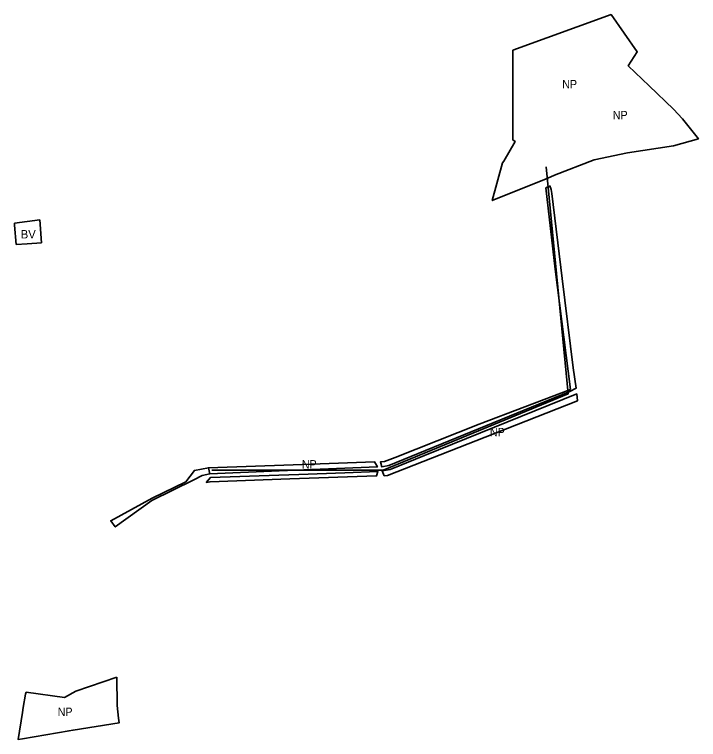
# Model space of a CAD drawing. Extents: x -650276 to -642489, y -1074311 to -1066658.
# Drawn here: x -643464 to -642489, y -1070593 to -1069560 of the extents above; entities that cross this region are included whole.
import ezdxf

# ---------------------------------------------------------------- set-up
doc = ezdxf.new("R2010")
doc.units = 0
doc.header["$LTSCALE"] = 4.8
for name, color, linetype, lineweight in [('15', 7, 'Continuous', 35), ('3', 7, 'Continuous', 35), ('48', 7, 'Continuous', 35), ('54', 7, 'Continuous', 35)]:
    doc.layers.add(name, color=color, linetype=linetype, lineweight=lineweight)
doc.layers.add('62', color=7, linetype='Continuous')

msp = doc.modelspace()

# ---------------------------------------------------------------- linework, layer by layer
at = {"layer": '15', "lineweight": 13}
for points in [[(-643461.327, -1069887.84), (-643445.37, -1069886.7), (-643425.253, -1069885.25), (-643427.6, -1069852.59), (-643463.51, -1069857.44)], [(-643463.51, -1069857.44), (-643463.31, -1069860.18), (-643461.327, -1069887.84)]]:
    msp.add_lwpolyline(points, dxfattribs=at)
at = {"layer": '3'}
msp.add_lwpolyline([(-643461.327, -1069887.84), (-643445.37, -1069886.7), (-643425.253, -1069885.25), (-643427.6, -1069852.59), (-643463.51, -1069857.44), (-643463.31, -1069860.18)], close=True, dxfattribs=at)
at = {"layer": '48'}
for points in [[(-642589.86, -1069757.1), (-642524.14, -1069746.8), (-642488.71, -1069736.85), (-642511.74, -1069708.63), (-642524.24, -1069694.66), (-642559.13, -1069661.18), (-642588.93, -1069632.86), (-642576, -1069613), (-642613.34, -1069559.68), (-642753.18, -1069610.65), (-642753.25, -1069738.59), (-642750.08, -1069740.57), (-642766.27, -1069769), (-642767.89, -1069771.42), (-642782.69, -1069824.93), (-642703.57, -1069792.88), (-642693.99, -1069788.85), (-642637.44, -1069766.81)], [(-642706.3, -1069806.69), (-642693.2, -1069922.89), (-642671.23, -1070094.16), (-642801.19, -1070143.75), (-642921.03, -1070191.32), (-642936.02, -1070197.23), (-642942.12, -1070197.4), (-642940.12, -1070204.42), (-642930.02, -1070202.54), (-642802.38, -1070150.51), (-642671.9, -1070097.32), (-642663.28, -1070092.67), (-642667.19, -1070063.71), (-642682.78, -1069935.98), (-642697.64, -1069815.14), (-642698.77, -1069809.17), (-642700.34, -1069804.12), (-642701.17, -1069804.49)], [(-642936.88, -1070217.27), (-642931.88, -1070217.1), (-642792.87, -1070162.36), (-642661.13, -1070110.48), (-642662.32, -1070100.64), (-642879.2, -1070188.43), (-642928.07, -1070208.21), (-642939.51, -1070210.35)], [(-643066.26, -1070201.69), (-643187.06, -1070205.98), (-643185.16, -1070214.62), (-643086.36, -1070210.57), (-642946.24, -1070204.83), (-642950.42, -1070197.58)], [(-643185.16, -1070214.62), (-643187.06, -1070205.98), (-643207.1, -1070209.72), (-643219.4, -1070225.8), (-643267.55, -1070249.49), (-643326.26, -1070281.43), (-643320, -1070290.2), (-643267.75, -1070252.77), (-643208.09, -1070223.14), (-643196.16, -1070217.22)], [(-643190.42, -1070226.99), (-643184.86, -1070225.91), (-643071.16, -1070221.95), (-642947.42, -1070217.64), (-642945.59, -1070211.49), (-642992.64, -1070213.18), (-643058.07, -1070215.38), (-643086.58, -1070216.57), (-643184.22, -1070220.08)]]:
    msp.add_lwpolyline(points, close=True, dxfattribs=at)
for points in [[(-643452.22, -1070592.35), (-643385.72, -1070580.86), (-643380.35, -1070580.14), (-643380.08, -1070580.09), (-643314.51, -1070569.69), (-643315.27, -1070563.2), (-643317.08, -1070544.75), (-643317.9, -1070504.73)], [(-643317.9, -1070504.73), (-643376.07, -1070524.59), (-643392.41, -1070533.68), (-643446.89, -1070526.01)], [(-643446.89, -1070526.01), (-643447.79, -1070528.63), (-643450.98, -1070547.74), (-643452.14, -1070554.77)], [(-643452.14, -1070554.77), (-643458.42, -1070593.43), (-643452.22, -1070592.35)]]:
    msp.add_lwpolyline(points, dxfattribs=at)
at = {"layer": '54'}
msp.add_lwpolyline([(-643182.326, -1070209.281), (-642937.896, -1070209.281), (-642674.665, -1070100.645), (-642706.002, -1069776.828)], dxfattribs=at)

# ---------------------------------------------------------------- texts
at = {"layer": '62', "width": 0.95}
for p in [(-642682.928, -1069665.096), (-642610.928, -1069709.096), (-642785.928, -1070161.096), (-643053.928, -1070207.096), (-643401.985, -1070559.967)]:
    msp.add_text('NP', height=12, dxfattribs=at).set_placement(p)
at = {"layer": '62'}
msp.add_text('BV', height=12, dxfattribs=at).set_placement((-643454.639, -1069879.037))

doc.saveas('drawing.dxf')
